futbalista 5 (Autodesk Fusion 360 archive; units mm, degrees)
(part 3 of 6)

design "futbalista 4" references "Raspberry Pi 4 Model B", "18650 battery variations", "rpiCameraMAssembly", "cam v2.1 rpi", "arduino nano strong", "light sensor", "stlpik", "25d-metal-gearmotor-34-47", "25d-metal-gearmotor-20.4", "BTS7960 43A HIGH POWER H BRIDGE MODULE", "Solenoid JF-0826B", "omniwheel"
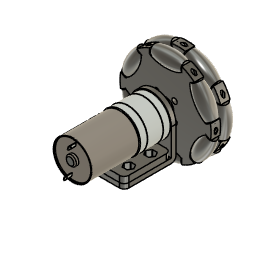
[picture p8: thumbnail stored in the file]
description: STEP AP214
part number: 25d-metal-gearmotor-20.4
component_insert "Component Insert3"
position "Position1"
position "Position3"
component_insert "Component Insert4"
sketch "Sketch3" plane through (0, 69.8, 0) normal (0, 1, 0) x axis (-1, 0, 0)
  line L1 (1.5, 1.3229) -> (1.5, -1.3229)
  line L2 (0, -20.25) -> (0, 13.15)
  line L3 (-13.15, -20.25) -> (-13.15, 0)
  line L4 (13.15, -20.25) -> (13.15, 0)
  line L5 (13.15, -20.25) -> (-13.15, -20.25)
  line L6 (0, -17.15) -> (0, -20.25)
  line L7 (13.15, -17.15) -> (-13.15, -17.15)
  arc A1 centre (0, 0) radius 2 clockwise from (1.5, -1.3229) to (1.5, 1.3229)
  circle C1 centre (0, 0) radius 11
  circle C2 centre (-5.5, 5.5) radius 1.5
  circle C3 centre (5.5, 5.5) radius 1.5
  circle C4 centre (-5.5, -5.5) radius 1.5
  circle C5 centre (5.5, -5.5) radius 1.5
  circle C6 centre (0, 0) radius 5
  circle C7 centre (0, 0) radius 13.15
  circle C8 centre (0, 0) radius 4
  circle C9 centre (-8.5, 0) radius 1.5
  circle C10 centre (8.5, 0) radius 1.5
  point P1 (0, 0)
  point P5 (0, 0)
  point P10 (0, 0)
  point P11 (0, 0)
  point P12 (-13.15, 0)
  point P16 (13.15, 0)
  point P18 (0, -17.15)
  point P19 (-13.15, -17.15)
  point P20 (13.15, -17.15)
  point P13 (0, 13.15)
  point P14 (0, -20.25)
  coincident P1 P5
  coincident P1 P10
  coincident P1 P11
  coincident C7 P12
  tangent C7 L3
  coincident C7 P16
  tangent C7 L4
  perpendicular L4 L5
  coincident L2 P18
  perpendicular L5 L6
  coincident L3 P19
  coincident L4 P20
  perpendicular L4 L7
  concentric C7 C8
  dimension "d21" diameter C7 = 26.3
  dimension "d24" distance P13 P14 = 33.4
  dimension "d25" distance P14 P18 = 3.1
  dimension "d30" diameter C9 = 3
  dimension "d31" diameter C10 = 3
  dimension "d13" R-Pattern1-uDistance = 11
  dimension "d14" R-Pattern1-vDistance = -11
extrude "Extrude1" new body sketch "Sketch3" profile of A1 L1 C1 C2 C3 C4 C5 along normal blind 3 bodies "motor adapter"
extrude "Extrude2" add sketch "Sketch3" profile of A1 L1 C6 against normal blind 10
extrude "Extrude3" new body sketch "Sketch3" profile of C1 C2 C3 C4 C5 C6 C7 L3 L4 L5 C8 C9 C10 against normal blind 12.5 and against normal blind 9.5 (= "12.50 mm - 3 mm") bodies "motor bracket"
chamfer "Chamfer1" distance 1.65
sketch "Sketch4" plane through (0, 0, -20.25) normal (0, 0, -1) x axis (1, 0, 0)
  line L1 (13.15, -60.3) -> (-13.15, -60.3)
  line L2 (13.15, -57.3) -> (13.15, -60.3)
  line L3 (-13.15, -57.3) -> (13.15, -57.3)
  line L4 (-13.15, -60.3) -> (-13.15, -57.3)
  line L5 (-13.15, -27.3) -> (13.15, -27.3)
  line L6 (-13.15, -57.3) -> (-13.15, -27.3)
  line L7 (13.15, -57.3) -> (13.15, -27.3)
  circle C1 centre (0, -42.35) radius 4.95
  circle C2 centre (-7.95, -35.45) radius 1.7
  circle C3 centre (7.95, -49.25) radius 1.7
  circle C4 centre (-7.95, -49.25) radius 1.7
  circle C5 centre (7.95, -35.45) radius 1.7
  point P5 (-13.15, -57.3)
  point P8 (-13.15, -57.3)
  point P4 (13.15, -57.3)
  point P9 (13.15, -57.3)
  point P3 (13.15, -60.3)
  point P6 (13.15, -27.3)
  perpendicular L4 L5
  coincident P5 P8
  perpendicular L3 L6
  coincident P4 P9
  perpendicular L3 L7
  dimension "d34" distance P3 P6 = 33
  dimension "d35" diameter C1 = 9.9
extrude "Extrude4" add sketch "Sketch4" profile of L3 L5 L6 L7 C1 C2 C3 C4 C5 against normal blind 3
fillet "Fillet1" radius 3
step "00000000-0000-0000-0000-000000000000" TotalAngle 360
circular_pattern "C-Pattern1" TotalAngle 360
component_insert "Component Insert2"
position "Position4"
position "Position6"
step "00000000-0000-0000-0000-000000000000" TotalAngle 360
sketch "Sketch1" plane through (0, 0, 0) normal (0, 0, 1) x axis (1, 0, 0)
  circle C1 centre (0, 0) radius 90
  point P1 (0, 0)
  point P2 (0, 0)
  coincident P1 P2
component_insert "Component Insert5"
sketch "Sketch5" plane through (0, 0, -20.25) normal (0, 0, -1) x axis (1, 0, 0)
  line L1 (-10.15, -27.3) -> (10.15, -27.3)
  line L2 (-13.15, -57.3) -> (-13.15, -30.3)
  line L3 (13.15, -57.3) -> (-13.15, -57.3)
  line L4 (13.15, -30.3) -> (13.15, -57.3)
  line L5 (-18.5675, 22.4402) -> (-28.7175, 4.8598)
  line L6 (-43.0483, 40.0382) -> (-19.6656, 26.5382)
  line L7 (-56.1983, 17.2618) -> (-43.0483, 40.0382)
  line L8 (-32.8156, 3.7618) -> (-56.1983, 17.2618)
  line L9 (28.7175, 4.8598) -> (18.5675, 22.4402)
  line L10 (56.1983, 17.2618) -> (32.8156, 3.7618)
  line L11 (43.0483, 40.0382) -> (56.1983, 17.2618)
  line L12 (19.6656, 26.5382) -> (43.0483, 40.0382)
  line L13 (6, 58.7) -> (11, 58.7)
  line L14 (6, 56.2) -> (6, 58.7)
  line L15 (-6, 56.2) -> (6, 56.2)
  line L16 (-6, 58.7) -> (-6, 56.2)
  line L17 (-11, 58.7) -> (-6, 58.7)
  line L18 (-11, 34.2) -> (-11, 58.7)
  line L19 (11, 34.2) -> (-11, 34.2)
  line L20 (11, 58.7) -> (11, 34.2)
  curve K1 (-5.4298, 52.2903) -> (-7.25, 53.7)
  curve K2 (-6, 54.95) -> (-4.5984, 53.1103)
  line L21 (-9.7646, -66.8) -> (-9.7646, -72.8)
  line L22 (9.7646, -66.8) -> (9.7646, -72.8)
  line L23 (9.7646, -66.8) -> (-9.7646, -66.8)
  line L24 (-30, -65.1664) -> (0, -65.1664)
  line L25 (30, -65.1664) -> (0, -65.1664)
  line L26 (30, -81.1311) -> (30, -65.1664)
  line L27 (-30, -81.1311) -> (-30, -65.1664)
  line L28 (85.2616, 14.5848) -> (71.4358, 6.6024)
  line L29 (71.4358, 6.6024) -> (56.4358, 32.5832)
  line L30 (41.4358, 58.564) -> (56.4358, 32.5832)
  line L31 (55.2616, 66.5463) -> (41.4358, 58.564)
  line L32 (-55.2616, 66.5463) -> (-41.4358, 58.564)
  line L33 (-41.4358, 58.564) -> (-56.4358, 32.5832)
  line L34 (-71.4358, 6.6024) -> (-56.4358, 32.5832)
  line L35 (-85.2616, 14.5848) -> (-71.4358, 6.6024)
  line L36 (-21.8303, 83.7) -> (0, 83.7)
  line L37 (21.8303, 83.7) -> (0, 83.7)
  line L38 (-1.3, 70.7) -> (0, 70.7)
  line L39 (-1.3, 78.7168) -> (-1.3, 70.7)
  line L40 (1.3, 70.7) -> (0, 70.7)
  line L41 (1.3, 78.7168) -> (1.3, 70.7)
  line L42 (6, 56.2) -> (-6, 56.2)
  line L43 (6, 57.7) -> (6, 56.2)
  line L44 (-6, 57.7) -> (6, 57.7)
  line L45 (-6, 56.2) -> (-6, 57.7)
  line L46 (11, 32.7) -> (11, 34.2)
  line L47 (-11, 34.2) -> (11, 34.2)
  line L48 (-11, 32.7) -> (-11, 34.2)
  line L49 (11, 32.7) -> (-11, 32.7)
  line L50 (45.6463, 41.5382) -> (43.0483, 40.0382)
  line L51 (56.1983, 17.2618) -> (43.0483, 40.0382)
  line L52 (56.1983, 17.2618) -> (58.7963, 18.7618)
  line L53 (45.6463, 41.5382) -> (58.7963, 18.7618)
  line L54 (-58.7963, 18.7618) -> (-56.1983, 17.2618)
  line L55 (-43.0483, 40.0382) -> (-56.1983, 17.2618)
  line L56 (-43.0483, 40.0382) -> (-45.6463, 41.5382)
  line L57 (-58.7963, 18.7618) -> (-45.6463, 41.5382)
  line L58 (13.15, -60.3) -> (13.15, -57.3)
  line L59 (-13.15, -57.3) -> (13.15, -57.3)
  line L60 (-13.15, -57.3) -> (-13.15, -60.3)
  line L61 (13.15, -60.3) -> (-13.15, -60.3)
  line L62 (-32, -74.955) -> (-32, -78.2065)
  line L63 (32, -74.955) -> (32, -78.2065)
  line L64 (80.9129, 9.7647) -> (83.7288, 11.3904)
  line L65 (48.9129, 65.1903) -> (51.7288, 66.816)
  line L66 (-48.9129, 65.1903) -> (-51.7288, 66.816)
  line L67 (-80.9129, 9.7647) -> (-83.7288, 11.3904)
  line L68 (22.0255, 78.4674) -> (22.0255, 81.579)
  line L69 (-22.0255, 78.4674) -> (-22.0255, 81.579)
  line L70 (-20.0255, 82.0928) -> (-20.0255, 79.0014)
  line L71 (20.0255, 82.0928) -> (20.0255, 79.0014)
  line L72 (20.0255, 84.15) -> (20.0255, 82.0928)
  line L73 (-20.0255, 84.15) -> (-20.0255, 82.0928)
  line L74 (-20.0255, 84.15) -> (-20.0255, 60.7)
  line L75 (20.0255, 60.7) -> (20.0255, 84.15)
  line L76 (-20.0255, 60.7) -> (20.0255, 60.7)
  line L77 (-74.5, 6) -> (-79.5, 6)
  line L78 (-74.5, -6) -> (-74.5, 6)
  line L79 (-79.5, -6) -> (-74.5, -6)
  line L80 (-79.5, 6) -> (-79.5, -6)
  line L81 (74.5, -6) -> (74.5, 6)
  line L82 (79.5, 6) -> (79.5, -6)
  line L83 (79.5, -6) -> (74.5, -6)
  line L84 (74.5, 6) -> (79.5, 6)
  line L85 (-32.0538, 67.5189) -> (-42.4462, 61.5189)
  line L86 (-42.4462, 61.5189) -> (-44.9462, 65.849)
  line L87 (-44.9462, 65.849) -> (-34.5538, 71.849)
  line L88 (-34.5538, 71.849) -> (-32.0538, 67.5189)
  line L89 (44.9462, -65.849) -> (42.4462, -61.5189)
  line L90 (34.5538, -71.849) -> (44.9462, -65.849)
  line L91 (42.4462, -61.5189) -> (32.0538, -67.5189)
  line L92 (32.0538, -67.5189) -> (34.5538, -71.849)
  line L93 (-42.4462, -61.5189) -> (-32.0538, -67.5189)
  line L94 (-32.0538, -67.5189) -> (-34.5538, -71.849)
  line L95 (-34.5538, -71.849) -> (-44.9462, -65.849)
  line L96 (-44.9462, -65.849) -> (-42.4462, -61.5189)
  line L97 (34.5538, 71.849) -> (32.0538, 67.5189)
  line L98 (44.9462, 65.849) -> (34.5538, 71.849)
  line L99 (32.0538, 67.5189) -> (42.4462, 61.5189)
  line L100 (42.4462, 61.5189) -> (44.9462, 65.849)
  line L101 (-74.5, 3) -> (-79.5, 3)
  line L102 (-74.5, -1) -> (-79.5, -1)
  line L103 (79.5, 3) -> (74.5, 3)
  line L104 (79.5, -1) -> (74.5, -1)
  line L105 (-42.3481, 67.349) -> (-39.8481, 63.0189)
  line L106 (-38.884, 69.349) -> (-36.384, 65.0189)
  line L107 (38.116, -64.0189) -> (40.616, -68.349)
  line L108 (34.6519, -66.0189) -> (37.1519, -70.349)
  line L109 (-37.1519, -70.349) -> (-34.6519, -66.0189)
  line L110 (-40.616, -68.349) -> (-38.116, -64.0189)
  line L111 (36.384, 65.0189) -> (38.884, 69.349)
  line L112 (39.8481, 63.0189) -> (42.3481, 67.349)
  curve K3 (4.75, 40.2) -> (6.5702, 38.7903)
  curve K4 (7.4016, 39.6103) -> (6, 41.45)
  arc A1 centre (10.15, -30.3) radius 3 clockwise from (10.15, -27.3) to (13.15, -30.3)
  arc A2 centre (-10.15, -30.3) radius 3 clockwise from (-13.15, -30.3) to (-10.15, -27.3)
  circle C1 centre (7.95, -35.45) radius 1.7
  circle C2 centre (0, -42.35) radius 4.95
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  point P1 (0, 0)
  point P54 (0, 0)
  point P56 (-9.7646, -66.8)
  point P59 (-9.7646, -66.8)
  point P58 (9.7646, -66.8)
  point P60 (9.7646, -66.8)
  point P107 (0, 0)
  point P163 (-79.5, 3)
  point P164 (-74.5, 3)
  point P165 (-79.5, -1)
  point P166 (-74.5, -1)
  point P167 (74.5, 3)
  point P168 (79.5, 3)
  point P169 (74.5, -1)
  point P170 (79.5, -1)
  point P81 (0, 70.7)
  point P84 (1.3, 70.7)
  point P134 (-74.5, 6)
  point P135 (-74.5, -6)
  coincident P1 P54
  coincident P56 P59
  coincident P58 P60
  parallel L23 L24
  perpendicular L2 L25
  perpendicular L25 L26
  perpendicular L24 L27
  perpendicular L38 L39
  perpendicular L39 L40
  perpendicular L40 L41
  coincident P1 P107
  vertical L68
  parallel L68 L69
  perpendicular L37 L72
  perpendicular L36 L73
  parallel L73 L74
  parallel L74 L75
  perpendicular L74 L76
  perpendicular L77 L78
  perpendicular L78 L79
  perpendicular L77 L80
  coincident L80 P163
  coincident L78 P164
  perpendicular L78 L101
  coincident L80 P165
  coincident L78 P166
  perpendicular L78 L102
  coincident L81 P167
  coincident L82 P168
  perpendicular L82 L103
  coincident L81 P169
  coincident L82 P170
  perpendicular L82 L104
  dimension "d53" distance P81 P84 = 1.3
  dimension "d62" diameter = 169
  dimension "d63" diameter = 163
  dimension "d78" distance P134 P135 = 12
  dimension "d49" C-Pattern1-Angle = 360
  dimension "d65" C-Pattern2-Angle = 360
  dimension "d80" C-Pattern3-Angle = 360
  dimension "d82" C-Pattern4-Angle = 360
  dimension "d84" C-Pattern5-Angle = 360
component_insert "Component Insert6"
position "Position7"
component_insert "Component Insert7"
step "00000000-0000-0000-0000-000000000000" TotalAngle 360
extrude "Extrude5" new body sketch "Sketch5" along normal blind 2
extrude "Extrude6" add sketch "Sketch5" against normal blind 3
offset_faces "OffsetFaces1" distance -0.2
sketch "Sketch6" plane through (0, -60.7, 0) normal (0, -1, 0) x axis (1, 0, 0)
  line L1 (-20.0255, -22.25) -> (-20.0255, -17.25)
  line L2 (20.0255, -22.25) -> (-20.0255, -22.25)
  line L3 (20.0255, -17.25) -> (20.0255, -22.25)
  line L4 (-20.0255, -17.25) -> (20.0255, -17.25)
  line L5 (-21.0255, -18.4) -> (-21.0255, -19.65)
  line L6 (-20.0255, -18.4) -> (-21.0255, -18.4)
  line L7 (-21.0255, -20.9) -> (-21.0255, -19.65)
  line L8 (-20.0255, -20.9) -> (-21.0255, -20.9)
  line L9 (20.0255, -18.4) -> (21.0255, -18.4)
  line L10 (21.0255, -18.4) -> (21.0255, -19.65)
  line L11 (20.0255, -20.9) -> (21.0255, -20.9)
  line L12 (21.0255, -20.9) -> (21.0255, -19.65)
  point P8 (-20.0255, -18.4)
  point P10 (-20.0255, -20.9)
  point P6 (-21.0255, -19.65)
  point P7 (-21.0255, -18.4)
  point P9 (-21.0255, -20.9)
  perpendicular L4 L5
  coincident L1 P8
  perpendicular L1 L6
  coincident L1 P10
  perpendicular L1 L8
  dimension "d70" distance P6 P7 = 1.25
  dimension "d71" distance P6 P9 = 1.25
extrude "Extrude7" cut sketch "Sketch6" profile of L1 L3 L5 L6 L7 L8 L9 L10 L11 L12 along normal blind 25
sketch "Sketch7" plane through (0, 0, -20.25) normal (0, 0, -1) x axis (1, 0, 0)
component_insert "Component Insert8"
position "Position13"
position "Position14"
component_insert "Component Insert9"
position "Position15"
position "Position18"
sketch "Sketch8" plane through (0, 0, -17.25) normal (0, 0, 1) x axis (-1, 0, 0)
  line L1 (-34.4806, 72.1222) -> (-45.2194, 65.9222)
  line L2 (-31.7806, 67.4457) -> (-34.4806, 72.1222)
  line L3 (-42.5194, 61.2457) -> (-31.7806, 67.4457)
  line L4 (-45.2194, 65.9222) -> (-42.5194, 61.2457)
  line L5 (-13.35, -30.3) -> (-13.35, -60.5)
  line L6 (10.15, -27.1) -> (-10.15, -27.1)
  line L7 (13.35, -60.5) -> (13.35, -30.3)
  line L8 (-13.35, -60.5) -> (13.35, -60.5)
  line L9 (-45.2194, -65.9222) -> (-34.4806, -72.1222)
  line L10 (-42.5194, -61.2457) -> (-45.2194, -65.9222)
  line L11 (-31.7806, -67.4457) -> (-42.5194, -61.2457)
  line L12 (-34.4806, -72.1222) -> (-31.7806, -67.4457)
  line L13 (74.3, -6.2) -> (79.7, -6.2)
  line L14 (74.3, 6.2) -> (74.3, -6.2)
  line L15 (79.7, 6.2) -> (74.3, 6.2)
  line L16 (79.7, -6.2) -> (79.7, 6.2)
  line L17 (32.9156, 3.5886) -> (59.0695, 18.6886)
  line L18 (18.3943, 22.3402) -> (28.5443, 4.7598)
  line L19 (45.7195, 41.8114) -> (19.5656, 26.7114)
  line L20 (59.0695, 18.6886) -> (45.7195, 41.8114)
  line L21 (32, -74.955) -> (32, -78.2065)
  line L22 (83.7288, 11.3904) -> (80.9129, 9.7647)
  line L23 (45.2194, -65.9222) -> (42.5194, -61.2457)
  line L24 (34.4806, -72.1222) -> (45.2194, -65.9222)
  line L25 (31.7806, -67.4457) -> (34.4806, -72.1222)
  line L26 (42.5194, -61.2457) -> (31.7806, -67.4457)
  line L27 (-74.3, 6.2) -> (-79.7, 6.2)
  line L28 (-74.3, -6.2) -> (-74.3, 6.2)
  line L29 (-79.7, -6.2) -> (-74.3, -6.2)
  line L30 (-79.7, 6.2) -> (-79.7, -6.2)
  line L31 (48.9129, 65.1903) -> (51.7288, 66.816)
  line L32 (22.0255, 81.579) -> (22.0255, 78.4674)
  line L33 (-19.5656, 26.7114) -> (-45.7195, 41.8114)
  line L34 (-28.5443, 4.7598) -> (-18.3943, 22.3402)
  line L35 (-59.0695, 18.6886) -> (-32.9156, 3.5886)
  line L36 (-45.7195, 41.8114) -> (-59.0695, 18.6886)
  line L37 (34.4806, 72.1222) -> (31.7806, 67.4457)
  line L38 (45.2194, 65.9222) -> (34.4806, 72.1222)
  line L39 (42.5194, 61.2457) -> (45.2194, 65.9222)
  line L40 (31.7806, 67.4457) -> (42.5194, 61.2457)
  line L41 (-11.2, 58.9) -> (-11.2, 32.5)
  line L42 (-5.8, 58.9) -> (-11.2, 58.9)
  line L43 (-5.8, 57.9) -> (-5.8, 58.9)
  line L44 (5.8, 57.9) -> (-5.8, 57.9)
  line L45 (5.8, 58.9) -> (5.8, 57.9)
  line L46 (11.2, 58.9) -> (5.8, 58.9)
  line L47 (11.2, 32.5) -> (11.2, 58.9)
  line L48 (-11.2, 32.5) -> (11.2, 32.5)
  line L49 (-22.0255, 78.4674) -> (-22.0255, 81.579)
  line L50 (-51.7288, 66.816) -> (-48.9129, 65.1903)
  line L51 (-80.9129, 9.7647) -> (-83.7288, 11.3904)
  line L52 (-32, -78.2065) -> (-32, -74.955)
  line L53 (-20.0255, 82.8712) -> (-20.0255, 60.7)
  line L54 (-41.4358, 58.564) -> (-55.2616, 66.5463)
  line L55 (-71.4358, 6.6024) -> (-41.4358, 58.564)
  line L56 (-85.2616, 14.5848) -> (-71.4358, 6.6024)
  line L57 (-30, -65.1664) -> (-30, -81.1311)
  line L58 (30, -65.1664) -> (-30, -65.1664)
  line L59 (30, -81.1311) -> (30, -65.1664)
  line L60 (71.4358, 6.6024) -> (85.2616, 14.5848)
  line L61 (41.4358, 58.564) -> (71.4358, 6.6024)
  line L62 (55.2616, 66.5463) -> (41.4358, 58.564)
  line L63 (20.0255, 60.7) -> (20.0255, 82.8712)
  line L64 (-20.0255, 60.7) -> (20.0255, 60.7)
  line L65 (55.1514, -55.9749) -> (76.0514, -19.7751)
  line L66 (49.6873, -57.439) -> (55.1514, -55.9749)
  line L67 (13.7473, -36.689) -> (49.6873, -57.439)
  line L68 (12.2832, -31.2249) -> (13.7473, -36.689)
  line L69 (33.1832, 4.9749) -> (12.2832, -31.2249)
  line L70 (38.6473, 6.439) -> (33.1832, 4.9749)
  line L71 (74.5873, -14.311) -> (38.6473, 6.439)
  line L72 (76.0514, -19.7751) -> (74.5873, -14.311)
  line L73 (-12.2832, -31.2249) -> (-33.1832, 4.9749)
  line L74 (-13.7473, -36.689) -> (-12.2832, -31.2249)
  line L75 (-49.6873, -57.439) -> (-13.7473, -36.689)
  line L76 (-55.1514, -55.9749) -> (-49.6873, -57.439)
  line L77 (-76.0514, -19.7751) -> (-55.1514, -55.9749)
  line L78 (-74.5873, -14.311) -> (-76.0514, -19.7751)
  line L79 (-38.6473, 6.439) -> (-74.5873, -14.311)
  line L80 (-33.1832, 4.9749) -> (-38.6473, 6.439)
  arc A1 centre (-10.15, -30.3) radius 3.2 clockwise from (-13.35, -30.3) to (-10.15, -27.1)
  arc A2 centre (10.15, -30.3) radius 3.2 clockwise from (10.15, -27.1) to (13.35, -30.3)
  arc A3 centre (31.3156, 6.3598) radius 3.2 clockwise from (32.9156, 3.5886) to (28.5443, 4.7598)
  arc A4 centre (21.1656, 23.9402) radius 3.2 clockwise from (18.3943, 22.3402) to (19.5656, 26.7114)
  arc A5 centre (0, 0) radius 81.5 clockwise from (80.9129, 9.7647) to (32, -74.955)
  arc A6 centre (0, 0) radius 84.5 clockwise from (83.7288, 11.3904) to (32, -78.2065)
  arc A7 centre (0, 0) radius 81.5 clockwise from (22.0255, 78.4674) to (48.9129, 65.1903)
  arc A8 centre (0, 0) radius 84.5 clockwise from (22.0255, 81.579) to (51.7288, 66.816)
  arc A9 centre (-21.1656, 23.9402) radius 3.2 clockwise from (-19.5656, 26.7114) to (-18.3943, 22.3402)
  arc A10 centre (-31.3156, 6.3598) radius 3.2 clockwise from (-28.5443, 4.7598) to (-32.9156, 3.5886)
  arc A11 centre (0, 0) radius 84.5 clockwise from (-51.7288, 66.816) to (-22.0255, 81.579)
  arc A12 centre (0, 0) radius 81.5 clockwise from (-48.9129, 65.1903) to (-22.0255, 78.4674)
  arc A13 centre (0, 0) radius 84.5 clockwise from (-32, -78.2065) to (-83.7288, 11.3904)
  arc A14 centre (0, 0) radius 81.5 clockwise from (-32, -74.955) to (-80.9129, 9.7647)
  arc A15 centre (0, 128.856) radius 50.156 clockwise from (-20.0255, 82.8712) to (-21.8303, 83.7)
  arc A16 centre (0, 0) radius 86.5 clockwise from (-55.2616, 66.5463) to (-21.8303, 83.7)
  arc A17 centre (0, 0) radius 86.5 clockwise from (-30, -81.1311) to (-85.2616, 14.5848)
  arc A18 centre (0, 0) radius 86.5 clockwise from (85.2616, 14.5848) to (30, -81.1311)
  arc A19 centre (0, 0) radius 86.5 clockwise from (21.8303, 83.7) to (55.2616, 66.5463)
  arc A20 centre (0, 128.856) radius 50.156 clockwise from (21.8303, 83.7) to (20.0255, 82.8712)
  circle C1 centre (54.6586, -34.3285) radius 1.6
  circle C2 centre (31.276, -20.8285) radius 1.6
  circle C3 centre (50.8378, -53.9463) radius 1.6
  circle C4 centre (16.1968, -33.9463) radius 1.6
  circle C5 centre (36.1968, 0.6947) radius 1.6
  circle C6 centre (70.8378, -19.3053) radius 1.6
  circle C7 centre (-31.276, -20.8285) radius 1.6
  circle C8 centre (-54.6586, -34.3285) radius 1.6
  circle C9 centre (-16.1968, -33.9463) radius 1.6
  circle C10 centre (-50.8378, -53.9463) radius 1.6
  circle C11 centre (-70.8378, -19.3053) radius 1.6
  circle C12 centre (-36.1968, 0.6947) radius 1.6
  circle C13 centre (29.0955, 71.0692) radius 1.5
  circle C14 centre (-29.0955, 71.0692) radius 1.5
  circle C15 centre (-76.0955, -10.3372) radius 1.5
  circle C16 centre (-47, -60.7321) radius 1.5
  circle C17 centre (47, -60.7321) radius 1.5
  circle C18 centre (76.0955, -10.3372) radius 1.5
  dimension "d133" C-Pattern1-Angle = 360
component_insert "Component Insert18"
component_insert "Component Insert19"
position "Position22"
step "00000000-0000-0000-0000-000000000000" TotalAngle 360
extrude "Extrude8" cut sketch "Sketch8" profile of C13 C14 C15 C16 C17 C18 against normal blind 5
offset_faces "OffsetFaces2" distance -0.2
offset_faces "OffsetFaces3" distance -0.3
chamfer "Chamfer2" distance 1.5
chamfer "Chamfer3" distance 1
position "Position8"
sketch "Sketch10" plane through (0, -60.7, 0) normal (0, -1, 0) x axis (1, 0, 0)
  line L1 (-20.0255, -17.4) -> (-20.0255, -17.25)
  line L2 (-21.0255, -18.4) -> (-20.0255, -17.4)
  line L3 (-21.0255, -20.9) -> (-21.0255, -18.4)
  line L4 (-20.0255, -21.9) -> (-21.0255, -20.9)
  line L5 (-20.0255, -22.25) -> (-20.0255, -21.9)
  line L6 (20.0255, -22.25) -> (-20.0255, -22.25)
  line L7 (20.0255, -21.9) -> (20.0255, -22.25)
  line L8 (21.0255, -20.9) -> (20.0255, -21.9)
  line L9 (21.0255, -18.4) -> (21.0255, -20.9)
  line L10 (20.0255, -17.4) -> (21.0255, -18.4)
  line L11 (20.0255, -17.25) -> (20.0255, -17.4)
  line L12 (-20.0255, -17.25) -> (20.0255, -17.25)
  line L13 (1.3, -4.3394) -> (1.3, -11.1606)
  line L14 (-1.3, -11.1606) -> (-1.3, -4.3394)
  line L15 (-20.0255, -7.75) -> (-20.0255, -17.25)
  line L16 (-20.0255, 1.75) -> (-20.0255, -7.75)
  line L17 (20.0255, 1.75) -> (-20.0255, 1.75)
  line L18 (20.0255, -17.25) -> (20.0255, 1.75)
  arc A1 centre (0, -7.75) radius 3.65 clockwise from (-1.3, -4.3394) to (1.3, -4.3394)
  arc A2 centre (0, -7.75) radius 3.65 clockwise from (1.3, -11.1606) to (-1.3, -11.1606)
  circle C1 centre (0, -7.75) radius 3.65
  point P2 (-20.0255, -17.25)
  point P19 (-20.0255, -17.25)
  point P13 (20.0255, -17.25)
  point P23 (20.0255, -17.25)
  point P15 (1.3, -4.3394)
  point P20 (-20.0255, -7.75)
  point P21 (-20.0255, 1.75)
  coincident P2 P19
  perpendicular L12 L15
  perpendicular L12 L16
  perpendicular L11 L17
  coincident P13 P23
  perpendicular L12 L18
  concentric A1 C1
  coincident P15 C1
  dimension "d95" distance P20 P21 = 9.5
extrude "Extrude9" new body sketch "Sketch10" profile of L1 L2 L3 L4 L5 L6 L7 L8 L9 L10 L11 L12 A1 A2 L15 L16 L17 L18 C1 along normal blind 7 bodies "kicker"
move "Move3"
sketch "Sketch11" plane through (1.3, 0, 0) normal (-1, 0, 0) x axis (0, -1, 0)
  line L1 (68.7, -4.3394) -> (68.7, -11.1606)
  line L2 (60.7, -4.3394) -> (68.7, -4.3394)
  line L3 (60.7, -11.1606) -> (60.7, -4.3394)
  line L4 (68.7, -11.1606) -> (60.7, -11.1606)
  line L5 (66.7, -11.4) -> (66.7, -4.1)
  line L6 (64.7, -4.1) -> (66.7, -4.1)
  line L7 (68.7, -4.1) -> (68.7, -4.3394)
  line L8 (66.7, -4.1) -> (68.7, -4.1)
  line L9 (66.7, -11.4) -> (64.7, -11.4)
  line L10 (68.7, -11.4) -> (66.7, -11.4)
  line L11 (68.7, -4.3394) -> (68.7, -11.4)
  line L12 (73.7, -4.1) -> (68.7, -4.1)
  line L13 (73.7, -11.4) -> (73.7, -4.1)
  line L14 (68.7, -11.4) -> (73.7, -11.4)
  line L15 (62.1902, -10.4002) -> (64.7, -7.75)
  line L16 (67.0472, -15) -> (62.1902, -10.4002)
  line L17 (73.7, -15) -> (67.0472, -15)
  line L18 (73.7, -11.4) -> (73.7, -15)
  circle C1 centre (64.7, -7.75) radius 1.5
  circle C2 centre (64.7, -7.75) radius 3.65
  point P8 (66.7, -4.1)
  point P10 (66.7, -4.1)
  point P11 (64.7, -4.1)
  point P3 (68.7, -4.3394)
  point P12 (68.7, -4.3394)
  point P14 (64.7, -11.4)
  point P9 (66.7, -11.4)
  point P15 (66.7, -11.4)
  point P16 (66.7, -11.4)
  point P7 (64.7, -7.75)
  point P20 (64.7, -7.75)
  point P21 (62.1902, -10.4002)
  point P13 (68.7, -4.1)
  point P18 (73.7, -4.1)
  concentric C1 C2
  coincident P8 P10
  coincident C2 P11
  tangent C2 L6
  coincident P3 P12
  perpendicular L6 L7
  perpendicular L5 L8
  coincident C2 P14
  coincident P9 P15
  tangent C2 L9
  coincident P9 P16
  perpendicular L5 L10
  perpendicular L2 L11
  perpendicular L7 L12
  perpendicular L10 L13
  perpendicular L11 L14
  coincident P7 P20
  coincident C2 P21
  tangent C2 L16
  perpendicular L13 L17
  perpendicular L14 L18
  dimension "d102" diameter C2 = 7.3
  dimension "d109" distance P13 P18 = 5
extrude "Extrude11" add sketch "Sketch11" profile of L1 L2 L4 C1 C2 L5 L6 L7 L8 L9 L10 L11 L12 L13 L14 L15 L16 L17 L18 along normal blind 2.6
move "Move4"
extrude "Extrude12" cut sketch "Sketch5" along normal blind 2 and against normal blind 22
offset_faces "OffsetFaces4" distance -0.2
extrude "Extrude14" new body sketch "Sketch5" against normal blind 55
sketch "Sketch12" plane through (0, 0, 0) normal (0, 1, 0) x axis (1, 0, 0)
  line L1 (30, 22.25) -> (30, 17.25)
  line L2 (-30, 22.25) -> (-30, 17.25)
  line L3 (30, 17.25) -> (30, 0)
  line L4 (32, 17.25) -> (30, 17.25)
  line L5 (32, 22.25) -> (32, 17.25)
  line L6 (30, 22.25) -> (32, 22.25)
  line L7 (-30, 17.25) -> (-30, 0)
  line L8 (-32, 17.25) -> (-30, 17.25)
  line L9 (-32, 22.25) -> (-32, 17.25)
  line L10 (-30, 22.25) -> (-32, 22.25)
  line L11 (30, 22.25) -> (-30, 22.25)
  circle C1 centre (0, 0) radius 30
  point P1 (0, 0)
  point P2 (0, 0)
  point P7 (30, 0)
  point P3 (30, 17.25)
  point P8 (30, 17.25)
  point P9 (30, 17.25)
  point P4 (30, 22.25)
  point P12 (30, 22.25)
  point P13 (-30, 0)
  point P5 (-30, 17.25)
  point P14 (-30, 17.25)
  point P6 (-30, 22.25)
  point P17 (-30, 22.25)
  point P18 (-30, 22.25)
  point P19 (30, 22.25)
  point P15 (-32, 17.25)
  coincident P1 P2
  coincident C1 P7
  coincident P3 P8
  coincident P3 P9
  perpendicular L1 L4
  perpendicular L4 L5
  coincident P4 P12
  perpendicular L1 L6
  coincident C1 P13
  coincident P5 P14
  perpendicular L7 L8
  perpendicular L8 L9
  coincident P6 P17
  perpendicular L2 L10
  coincident P6 P18
  coincident P4 P19
  dimension "d117" distance P14 P15 = 2
extrude "Extrude15" cut sketch "Sketch12" along normal blind 85
circular_pattern "C-Pattern2" TotalAngle 360
sketch "Sketch13" plane through (0, -76.7, 0) normal (0, 1, 0) x axis (-1, 0, 0)
  line L1 (19.8255, 1.75) -> (19.8255, -17.4828)
  line L2 (-19.8255, 1.75) -> (19.8255, 1.75)
  line L3 (-19.8255, -17.4828) -> (-19.8255, 1.75)
  line L4 (-20.8255, -18.4828) -> (-19.8255, -17.4828)
  line L5 (-20.8255, -20.8172) -> (-20.8255, -18.4828)
  line L6 (-19.8255, -21.8172) -> (-20.8255, -20.8172)
  line L7 (-19.8255, -22.25) -> (-19.8255, -21.8172)
  line L8 (19.8255, -22.25) -> (-19.8255, -22.25)
  line L9 (19.8255, -21.8172) -> (19.8255, -22.25)
  line L10 (20.8255, -20.8172) -> (19.8255, -21.8172)
  line L11 (20.8255, -18.4828) -> (20.8255, -20.8172)
  line L12 (19.8255, -17.4828) -> (20.8255, -18.4828)
  line L13 (-1.1, -4.1) -> (-1.1, -4.0605)
  line L14 (1.1, -4.1) -> (-1.1, -4.1)
  line L15 (1.1, -4.0605) -> (1.1, -4.1)
  line L16 (1.1, -14.6711) -> (1.1, -11.4395)
  line L17 (-1.1, -14.6711) -> (1.1, -14.6711)
  line L18 (-1.1, -11.4395) -> (-1.1, -14.6711)
  line L19 (0, -22.25) -> (0, -7.75)
  line L20 (0, 6.75) -> (0, -7.75)
  line L21 (-19.8255, 6.75) -> (0, 6.75)
  line L22 (-19.8255, 1.75) -> (-19.8255, 6.75)
  line L23 (19.8255, 6.75) -> (0, 6.75)
  line L24 (19.8255, 1.75) -> (19.8255, 6.75)
  line L25 (22.0255, -17.25) -> (22.0255, -20.25)
  line L26 (-22.0255, -17.25) -> (-22.0255, -20.25)
  line L27 (0, -20.25) -> (22.0255, -20.25)
  line L28 (-22.0255, -20.25) -> (0, -20.25)
  line L29 (-19.8255, -17.25) -> (-22.0255, -17.25)
  line L30 (19.8255, -17.25) -> (22.0255, -17.25)
  arc A1 centre (0, -7.75) radius 3.85 clockwise from (1.1, -4.0605) to (1.1, -11.4395)
  arc A2 centre (0, -7.75) radius 3.85 clockwise from (-1.1, -11.4395) to (-1.1, -4.0605)
  point P19 (0, -7.75)
  point P23 (0, -7.75)
  point P24 (0, -22.25)
  point P4 (-19.8255, 1.75)
  point P27 (-19.8255, 1.75)
  point P3 (19.8255, 1.75)
  point P29 (19.8255, 1.75)
  point P30 (22.0255, -20.25)
  point P34 (22.0255, -20.25)
  point P35 (0, -20.25)
  point P32 (-22.0255, -20.25)
  point P36 (-22.0255, -20.25)
  point P33 (-22.0255, -17.25)
  point P37 (-22.0255, -17.25)
  point P38 (-19.8255, -17.25)
  point P31 (22.0255, -17.25)
  point P39 (22.0255, -17.25)
  point P25 (0, 6.75)
  coincident P19 P23
  midpoint L8 P24
  perpendicular L14 L20
  perpendicular L3 L21
  coincident P4 P27
  perpendicular L2 L22
  perpendicular L1 L23
  coincident P3 P29
  perpendicular L2 L24
  coincident P30 P34
  coincident L19 P35
  perpendicular L19 L27
  coincident P32 P36
  coincident P33 P37
  coincident L3 P38
  perpendicular L3 L29
  coincident P31 P39
  perpendicular L1 L30
  dimension "d120" distance P23 P25 = 14.5
extrude "Extrude16" cut sketch "Sketch13" profile of L1 L2 L3 L4 L5 L11 L12 L13 L14 L15 A1 L16 L17 L18 A2 L19 L20 L21 L22 L23 L24 L25 L26 L27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 against normal blind 10
extrude "Extrude17" add of existing geometry blind 5
offset_faces "OffsetFaces5" distance -0.3
fillet "Fillet2" radius 1.5
component_insert "Component Insert11"
position "Position9"
position "Position10"
component_insert "Component Insert12"
component_insert "Component Insert13"
component_insert "Component Insert14"
position "Position11"
component_insert "Component Insert15"
position "Position12"
position "Position19"
position "Position20"
component_insert "Component Insert17"
position "Position21"
position "Position23"
position "Position38"
position "Position39"
position "Position40"
sketch "Sketch40" plane through (57.7098, 10.1758, 0) normal (-0.9848, -0.1736, 0) x axis (0.1736, -0.9848, 0)
  line L1 (-57.3849, -14) -> (-57.3849, 36)
  line L2 (24.6151, -17) -> (-54.3849, -17)
  line L3 (27.6151, 36) -> (27.6151, -14)
  line L4 (-54.3849, 39) -> (24.6151, 39)
  line L5 (-36.8849, -10.5) -> (-30.8849, -10.5)
  line L6 (-36.8849, -16.5) -> (-36.8849, -10.5)
  line L7 (-30.8849, -16.5) -> (-36.8849, -16.5)
  line L8 (-30.8849, -10.5) -> (-30.8849, -16.5)
  line L9 (-36.8849, -16.5) -> (-30.8849, -10.5)
  line L10 (-30.8849, -16.5) -> (-36.8849, -10.5)
  line L11 (27.1151, -16.5) -> (21.1151, -16.5)
  line L12 (27.1151, -10.5) -> (27.1151, -16.5)
  line L13 (21.1151, -10.5) -> (27.1151, -10.5)
  line L14 (21.1151, -16.5) -> (21.1151, -10.5)
  line L15 (-30.8849, 32.5) -> (-36.8849, 32.5)
  line L16 (-30.8849, 38.5) -> (-30.8849, 32.5)
  line L17 (-36.8849, 38.5) -> (-30.8849, 38.5)
  line L18 (-36.8849, 32.5) -> (-36.8849, 38.5)
  line L19 (27.1151, 32.5) -> (21.1151, 32.5)
  line L20 (27.1151, 38.5) -> (27.1151, 32.5)
  line L21 (21.1151, 38.5) -> (27.1151, 38.5)
  line L22 (21.1151, 32.5) -> (21.1151, 38.5)
  line L23 (-66.2709, -17.25) -> (-69.6709, -17.25)
  line L24 (76.7419, -17.25) -> (73.3419, -17.25)
  line L25 (-49.9479, -17.25) -> (-53.3479, -17.25)
  line L26 (-21.694, -17.25) -> (-25.094, -17.25)
  line L27 (66.6371, -17.25) -> (63.2371, -17.25)
  line L28 (4.7337, -17.25) -> (1.3337, -17.25)
  line L29 (77.3985, -17.25) -> (72.9523, -17.25)
  line L30 (71.7604, -17.25) -> (77.3985, -17.25)
  line L31 (67.3141, -17.25) -> (71.7604, -17.25)
  line L32 (72.9523, -17.25) -> (67.3141, -17.25)
  line L33 (-27.5215, -17.25) -> (-57.2627, -17.25)
  line L34 (-24.8771, -17.25) -> (-27.5215, -17.25)
  line L35 (-28.4508, -17.25) -> (-24.9258, -17.25)
  line L36 (-28.4508, -17.25) -> (-32.1579, -17.25)
  line L37 (-61.8991, -17.25) -> (-32.1579, -17.25)
  line L38 (-57.2627, -17.25) -> (-61.8991, -17.25)
  line L39 (-57.1054, -17.25) -> (-65.4617, -17.25)
  line L40 (-52.5092, -17.25) -> (-57.1054, -17.25)
  line L41 (-60.8654, -17.25) -> (-52.5092, -17.25)
  line L42 (-65.4617, -17.25) -> (-60.8654, -17.25)
  line L43 (-19.2512, -17.25) -> (-20.2931, -17.25)
  line L44 (-6.4487, -17.25) -> (-19.2512, -17.25)
  line L45 (-7.4906, -17.25) -> (-6.4487, -17.25)
  line L46 (-20.2931, -17.25) -> (-7.4906, -17.25)
  line L47 (-2.1817, -17.25) -> (8.1473, -17.25)
  line L48 (-0.2691, -17.25) -> (-2.3747, -17.25)
  line L49 (18.8066, -17.25) -> (-0.2691, -17.25)
  line L50 (22.9081, -17.25) -> (18.8066, -17.25)
  line L51 (33.2371, -17.25) -> (22.9081, -17.25)
  line L52 (8.1473, -17.25) -> (33.2371, -17.25)
  line L53 (-79.373, -17.25) -> (-82.5751, -17.25)
  line L54 (-79.373, -17.25) -> (-4.434, -17.25)
  line L55 (-3.322, -17.25) -> (-4.434, -17.25)
  line L56 (-3.322, -17.25) -> (-82.5751, -17.25)
  line L57 (-72.9523, -17.25) -> (-67.3141, -17.25)
  line L58 (-77.3985, -17.25) -> (-72.9523, -17.25)
  line L59 (-71.7604, -17.25) -> (-77.3985, -17.25)
  line L60 (-67.3141, -17.25) -> (-71.7604, -17.25)
  line L61 (19.2512, -17.25) -> (20.2931, -17.25)
  line L62 (6.4487, -17.25) -> (19.2512, -17.25)
  line L63 (7.4906, -17.25) -> (6.4487, -17.25)
  line L64 (20.2931, -17.25) -> (7.4906, -17.25)
  line L65 (55.7063, -17.25) -> (56.8183, -17.25)
  line L66 (55.7063, -17.25) -> (73.4506, -17.25)
  line L67 (76.5149, -17.25) -> (73.4506, -17.25)
  line L68 (76.5149, -17.25) -> (56.8183, -17.25)
  line L69 (29.7032, -17.25) -> (49.1153, -17.25)
  line L70 (29.7032, -17.25) -> (25.1949, -17.25)
  line L71 (9.6442, -17.25) -> (25.1949, -17.25)
  line L72 (9.6442, -17.25) -> (8.5011, -17.25)
  line L73 (28.662, -17.25) -> (9.2498, -17.25)
  line L74 (49.1153, -17.25) -> (28.662, -17.25)
  line L75 (65.4617, -17.25) -> (60.8654, -17.25)
  line L76 (57.1054, -17.25) -> (65.4617, -17.25)
  line L77 (52.5092, -17.25) -> (57.1054, -17.25)
  line L78 (60.8654, -17.25) -> (52.5092, -17.25)
  line L79 (60.2976, -17.25) -> (33.7078, -17.25)
  line L80 (59.2557, -17.25) -> (60.2976, -17.25)
  line L81 (58.2709, -17.25) -> (59.2557, -17.25)
  line L82 (56.3607, -17.25) -> (58.2709, -17.25)
  line L83 (57.3456, -17.25) -> (56.3607, -17.25)
  line L84 (56.3037, -17.25) -> (57.3456, -17.25)
  line L85 (29.7139, -17.25) -> (56.3037, -17.25)
  line L86 (33.7078, -17.25) -> (29.7139, -17.25)
  line L87 (84.1643, -17.25) -> (74.7836, -17.25)
  line L88 (81.1, -17.25) -> (84.1643, -17.25)
  line L89 (72.6936, -17.25) -> (81.1, -17.25)
  line L90 (74.7836, -17.25) -> (72.6936, -17.25)
  line L91 (25.7567, -17.25) -> (-71.4616, -17.25)
  line L92 (23.6667, -17.25) -> (25.7567, -17.25)
  line L93 (-68.2595, -17.25) -> (23.6667, -17.25)
  line L94 (-71.4616, -17.25) -> (-68.2595, -17.25)
  line L95 (85.0896, -17.25) -> (63.2552, -17.25)
  line L96 (86.2192, -17.25) -> (85.0896, -17.25)
  line L97 (75.1314, -17.25) -> (86.2192, -17.25)
  line L98 (64.8695, -17.25) -> (75.1314, -17.25)
  line L99 (18.9068, -17.25) -> (64.8695, -17.25)
  line L100 (29.1687, -17.25) -> (18.9068, -17.25)
  line L101 (-74.6891, -17.25) -> (29.1687, -17.25)
  line L102 (-58.9669, -17.25) -> (-74.6891, -17.25)
  line L103 (-69.3858, -17.25) -> (-58.9669, -17.25)
  line L104 (-85.108, -17.25) -> (-69.3858, -17.25)
  line L105 (-85.108, -17.25) -> (-0.4423, -17.25)
  line L106 (-5.9026, -17.25) -> (-0.4423, -17.25)
  line L107 (50.479, -17.25) -> (-5.9026, -17.25)
  line L108 (55.9392, -17.25) -> (50.479, -17.25)
  line L109 (55.9392, -17.25) -> (78.6376, -17.25)
  line L110 (78.6376, -17.25) -> (78.1348, -17.25)
  line L111 (56.3004, -17.25) -> (78.1348, -17.25)
  line L112 (63.2552, -17.25) -> (56.3004, -17.25)
  line L113 (-36.9174, -17.25) -> (-36.8849, -16.5)
  line L114 (-30.8849, -16.5) -> (-30.8849, -17.25)
  line L115 (21.0826, -17.25) -> (21.1151, -16.5)
  line L116 (27.1151, -16.5) -> (27.1151, -17.25)
  arc A1 centre (-54.3849, -14) radius 3 clockwise from (-54.3849, -17) to (-57.3849, -14)
  arc A2 centre (24.6151, -14) radius 3 clockwise from (27.6151, -14) to (24.6151, -17)
  arc A3 centre (24.6151, 36) radius 3 clockwise from (24.6151, 39) to (27.6151, 36)
  arc A4 centre (-54.3849, 36) radius 3 clockwise from (-57.3849, 36) to (-54.3849, 39)
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  point P73 (-33.8849, -13.5)
  point P65 (-33.8849, -13.5)
  point P185 (-36.9174, -17.25)
  point P186 (-30.8849, -17.25)
  point P71 (-36.8849, -16.5)
  point P72 (-30.8849, -16.5)
  point P70 (-36.8849, -10.5)
  horizontal L5
  perpendicular L5 L6
  parallel L5 L7
  parallel L6 L8
  coincident L9 P73
  coincident L10 P73
  coincident P65 P73
  coincident L56 P185
  coincident L36 P186
  dimension "d313" diameter = 3.4
  dimension "d318" distance P71 P72 = 6
  dimension "d319" distance P70 P71 = 6
  dimension "d316" R-Pattern1-uDistance = 58
  dimension "d317" R-Pattern1-vDistance = 49
extrude "Extrude58" add sketch "Sketch40" along normal blind 5
extrude "Extrude59" add of existing geometry blind 3.5 second side blind -1.6
sketch "Sketch41" plane through (-22.151, 0, 0) normal (1, 0, 0) x axis (0, 1, 0)
  line L1 (55.9417, 28.85) -> (55.9417, -12.65)
  line L2 (51.9417, 32.85) -> (55.9417, 28.85)
  line L3 (10.1417, 32.85) -> (51.9417, 32.85)
  line L4 (6.1417, 28.85) -> (10.1417, 32.85)
  line L5 (6.1417, -12.65) -> (6.1417, 28.85)
  line L6 (10.1417, -16.65) -> (6.1417, -12.65)
  line L7 (51.9417, -16.65) -> (10.1417, -16.65)
  line L8 (55.9417, -12.65) -> (51.9417, -16.65)
  line L9 (9.3417, -14.9) -> (15.3417, -14.9)
  line L10 (9.3417, -8.9) -> (9.3417, -14.9)
  line L11 (15.3417, -8.9) -> (9.3417, -8.9)
  line L12 (15.3417, -14.9) -> (15.3417, -8.9)
  line L13 (9.3417, -8.9) -> (15.3417, -14.9)
  line L14 (15.3417, -8.9) -> (9.3417, -14.9)
  line L15 (46.8102, -17.25) -> (40.8693, -17.25)
  line L16 (47.1401, -17.25) -> (46.8102, -17.25)
  line L17 (41.1992, -17.25) -> (47.1401, -17.25)
  line L18 (40.8693, -17.25) -> (41.1992, -17.25)
  line L19 (-10.3087, -17.25) -> (-16.2495, -17.25)
  line L20 (-9.9787, -17.25) -> (-10.3087, -17.25)
  line L21 (-15.9196, -17.25) -> (-9.9787, -17.25)
  line L22 (-16.2495, -17.25) -> (-15.9196, -17.25)
  line L23 (39.7232, -17.25) -> (40.5915, -17.25)
  line L24 (45.6641, -17.25) -> (39.7232, -17.25)
  line L25 (46.5323, -17.25) -> (45.6641, -17.25)
  line L26 (40.5915, -17.25) -> (46.5323, -17.25)
  line L27 (-17.3956, -17.25) -> (-16.5274, -17.25)
  line L28 (-11.4548, -17.25) -> (-17.3956, -17.25)
  line L29 (-10.5865, -17.25) -> (-11.4548, -17.25)
  line L30 (-16.5274, -17.25) -> (-10.5865, -17.25)
  line L31 (62.4321, -17.25) -> (59.0321, -17.25)
  line L32 (-69.3692, -17.25) -> (-72.7692, -17.25)
  line L33 (62.4321, -17.25) -> (59.0321, -17.25)
  line L34 (12.0372, -17.25) -> (8.6372, -17.25)
  line L35 (-69.3692, -17.25) -> (-72.7692, -17.25)
  line L36 (12.0372, -17.25) -> (8.6372, -17.25)
  line L37 (-72.532, -17.25) -> (-66.032, -17.25)
  line L38 (-67.3359, -17.25) -> (-72.532, -17.25)
  line L39 (-60.8359, -17.25) -> (-67.3359, -17.25)
  line L40 (-66.032, -17.25) -> (-60.8359, -17.25)
  line L41 (30.3, -17.25) -> (60.5, -17.25)
  line L42 (30.3, -17.25) -> (27.1, -17.25)
  line L43 (30.3, -17.25) -> (27.1, -17.25)
  line L44 (60.5, -17.25) -> (30.3, -17.25)
  line L45 (66.032, -17.25) -> (72.532, -17.25)
  line L46 (60.8359, -17.25) -> (66.032, -17.25)
  line L47 (67.3359, -17.25) -> (60.8359, -17.25)
  line L48 (72.532, -17.25) -> (67.3359, -17.25)
  line L49 (-6.5, -17.25) -> (6.5, -17.25)
  line L50 (6.5, -17.25) -> (-6.5, -17.25)
  line L51 (-3.5886, -17.25) -> (-18.6886, -17.25)
  line L52 (-3.1598, -17.25) -> (-4.7598, -17.25)
  line L53 (-22.3402, -17.25) -> (-4.7598, -17.25)
  line L54 (-22.3402, -17.25) -> (-26.7114, -17.25)
  line L55 (-41.8114, -17.25) -> (-26.7114, -17.25)
  line L56 (-18.6886, -17.25) -> (-41.8114, -17.25)
  line L57 (74.955, -17.25) -> (78.2065, -17.25)
  line L58 (-9.7647, -17.25) -> (74.955, -17.25)
  line L59 (-11.3904, -17.25) -> (-9.7647, -17.25)
  line L60 (78.2065, -17.25) -> (-11.3904, -17.25)
  line L61 (66.032, -17.25) -> (60.8359, -17.25)
  line L62 (72.532, -17.25) -> (66.032, -17.25)
  line L63 (67.3359, -17.25) -> (72.532, -17.25)
  line L64 (60.8359, -17.25) -> (67.3359, -17.25)
  line L65 (6.5, -17.25) -> (-6.5, -17.25)
  line L66 (-6.5, -17.25) -> (6.5, -17.25)
  line L67 (-65.1903, -17.25) -> (-66.816, -17.25)
  line L68 (-78.4674, -17.25) -> (-65.1903, -17.25)
  line L69 (-81.579, -17.25) -> (-78.4674, -17.25)
  line L70 (-66.816, -17.25) -> (-81.579, -17.25)
  line L71 (-26.7114, -17.25) -> (-41.8114, -17.25)
  line L72 (-22.3402, -17.25) -> (-26.7114, -17.25)
  line L73 (-4.7598, -17.25) -> (-22.3402, -17.25)
  line L74 (-3.1598, -17.25) -> (-4.7598, -17.25)
  line L75 (-18.6886, -17.25) -> (-3.5886, -17.25)
  line L76 (-41.8114, -17.25) -> (-18.6886, -17.25)
  line L77 (-72.532, -17.25) -> (-67.3359, -17.25)
  line L78 (-66.032, -17.25) -> (-72.532, -17.25)
  line L79 (-60.8359, -17.25) -> (-66.032, -17.25)
  line L80 (-67.3359, -17.25) -> (-60.8359, -17.25)
  line L81 (-59.2, -17.25) -> (-32.2, -17.25)
  line L82 (-58.2, -17.25) -> (-59.2, -17.25)
  line L83 (-59.2, -17.25) -> (-58.2, -17.25)
  line L84 (-32.2, -17.25) -> (-59.2, -17.25)
  line L85 (-66.816, -17.25) -> (-81.579, -17.25)
  line L86 (-78.4674, -17.25) -> (-81.579, -17.25)
  line L87 (-78.4674, -17.25) -> (-65.1903, -17.25)
  line L88 (-66.816, -17.25) -> (-65.1903, -17.25)
  line L89 (78.2065, -17.25) -> (-11.3904, -17.25)
  line L90 (-9.7647, -17.25) -> (-11.3904, -17.25)
  line L91 (-9.7647, -17.25) -> (74.955, -17.25)
  line L92 (78.2065, -17.25) -> (74.955, -17.25)
  line L93 (-82.8712, -17.25) -> (-60.7, -17.25)
  line L94 (-82.8712, -17.25) -> (-83.7, -17.25)
  line L95 (-83.7, -17.25) -> (-66.5463, -17.25)
  line L96 (-58.564, -17.25) -> (-66.5463, -17.25)
  line L97 (-6.6024, -17.25) -> (-58.564, -17.25)
  line L98 (-14.5848, -17.25) -> (-6.6024, -17.25)
  line L99 (-14.5848, -17.25) -> (81.1311, -17.25)
  line L100 (65.1664, -17.25) -> (81.1311, -17.25)
  line L101 (81.1311, -17.25) -> (65.1664, -17.25)
  line L102 (-14.5848, -17.25) -> (81.1311, -17.25)
  line L103 (-6.6024, -17.25) -> (-14.5848, -17.25)
  line L104 (-58.564, -17.25) -> (-6.6024, -17.25)
  line L105 (-66.5463, -17.25) -> (-58.564, -17.25)
  line L106 (-83.7, -17.25) -> (-66.5463, -17.25)
  line L107 (-82.8712, -17.25) -> (-83.7, -17.25)
  line L108 (-60.7, -17.25) -> (-82.8712, -17.25)
  line L109 (9.3417, -14.9) -> (9.3417, -17.25)
  line L110 (15.3417, -14.9) -> (15.3417, -17.25)
  line L111 (55.3417, -14.9) -> (55.3417, -17.25)
  line L112 (49.3417, -14.9) -> (49.3417, -17.25)
  line L113 (49.3417, -14.9) -> (55.3417, -14.9)
  line L114 (49.3417, -8.9) -> (49.3417, -14.9)
  line L115 (55.3417, -8.9) -> (49.3417, -8.9)
  line L116 (55.3417, -14.9) -> (55.3417, -8.9)
  circle C1 centre (33.4417, 21.6) radius 1.6
  circle C2 centre (33.4417, -5.4) radius 1.6
  circle C3 centre (52.3417, 28.1) radius 1.6
  circle C4 centre (52.3417, -11.9) radius 1.6
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  point P20 (12.3417, -11.9)
  point P14 (12.3417, -11.9)
  point P83 (9.3417, -17.25)
  point P84 (15.3417, -17.25)
  point P92 (12.3417, -11.9)
  point P18 (9.3417, -8.9)
  point P19 (15.3417, -8.9)
  point P86 (55.3417, -8.9)
  point P89 (49.3417, -8.9)
  horizontal L9
  perpendicular L9 L10
  parallel L9 L11
  parallel L10 L12
  coincident L13 P20
  coincident L14 P20
  coincident P14 P20
  coincident L34 P83
  coincident L102 P84
  horizontal L113
  perpendicular L113 L114
  parallel L113 L115
  parallel L114 L116
  coincident P20 P92
  dimension "d326" distance P18 P19 = 6
  dimension "d327" distance P86 P89 = 6
  dimension "d328" diameter = 3.4
  dimension "d329" diameter = 3.4
extrude "Extrude60" add sketch "Sketch41" along normal blind 6 and against normal blind 37
extrude "Extrude61" cut of existing geometry blind -5.3 second side blind 37
fillet "Fillet5" radius 2.5
offset_faces "OffsetFaces20" distance -0.2
position "Position41"
position "Position42"
sketch "Sketch43" plane through (0, -13.8152, 2) normal (0, -1, 0) x axis (1, 0, 0)
  line L1 (12.1244, 49.23) -> (21.1244, 33.6416)
  line L2 (-21.1244, 33.6416) -> (-12.1244, 49.23)
  line L3 (9, 12.6416) -> (-9, 12.6416)
  line L4 (23, -19.25) -> (23, 26.6416)
  line L5 (-23, -19.25) -> (-23, 26.6416)
  line L6 (23, -19.25) -> (-23, -19.25)
  line L7 (13.15, -19.25) -> (-13.15, -19.25)
  line L8 (13.15, -2) -> (13.15, -19.25)
  line L9 (-13.15, -19.25) -> (-13.15, -2)
  line L10 (-23, 12.6416) -> (-9, 12.6416)
  line L11 (23, 12.6416) -> (9, 12.6416)
  arc A1 centre (0, 42.23) radius 14 clockwise from (-12.1244, 49.23) to (12.1244, 49.23)
  arc A2 centre (-9, 26.6416) radius 14 clockwise from (-9, 12.6416) to (-21.1244, 33.6416)
  arc A3 centre (9, 26.6416) radius 14 clockwise from (21.1244, 33.6416) to (9, 12.6416)
  arc A4 centre (0, -2) radius 13.15 clockwise from (-13.15, -2) to (13.15, -2)
  circle C1 centre (0, -2) radius 4
  circle C2 centre (-8.5, -2) radius 1.5
  circle C3 centre (8.5, -2) radius 1.5
  point P11 (23, 26.6416)
  point P13 (-23, 26.6416)
  point P7 (-9, 12.6416)
  point P22 (-9, 12.6416)
  point P23 (-23, 12.6416)
  point P9 (9, 12.6416)
  point P24 (9, 12.6416)
  point P25 (23, 12.6416)
  coincident A3 P11
  tangent A3 L4
  coincident A2 P13
  tangent A2 L5
  coincident P7 P22
  coincident L5 P23
  tangent A2 L10
  coincident P9 P24
  coincident L4 P25
  tangent A3 L11
  perpendicular L4 L11
extrude "Extrude62" add sketch "Sketch43" profile of A2 L3 A3 L4 L5 L6 L7 L8 A4 L9 C1 C2 C3 L10 L11 against normal blind 35 and along normal blind 18.3848
extrude "Extrude63" cut sketch "Sketch43" profile of L6 L7 L8 A4 L9 C1 C2 C3 against normal blind 75 and against normal blind 13.815
circular_pattern "C-Pattern4" TotalAngle 360
offset_faces "OffsetFaces21" distance -0.2
position "Position43"
position "Position45"
combine "Combine3"
extrude "Extrude64" cut sketch "Sketch43" profile of A2 A3 L4 L5 L10 L11 along normal blind 18.385
chamfer "Chamfer5" distance 10
combine "Combine4"
extrude "Extrude65" cut sketch "Sketch41" along normal blind 22 and against normal blind 5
